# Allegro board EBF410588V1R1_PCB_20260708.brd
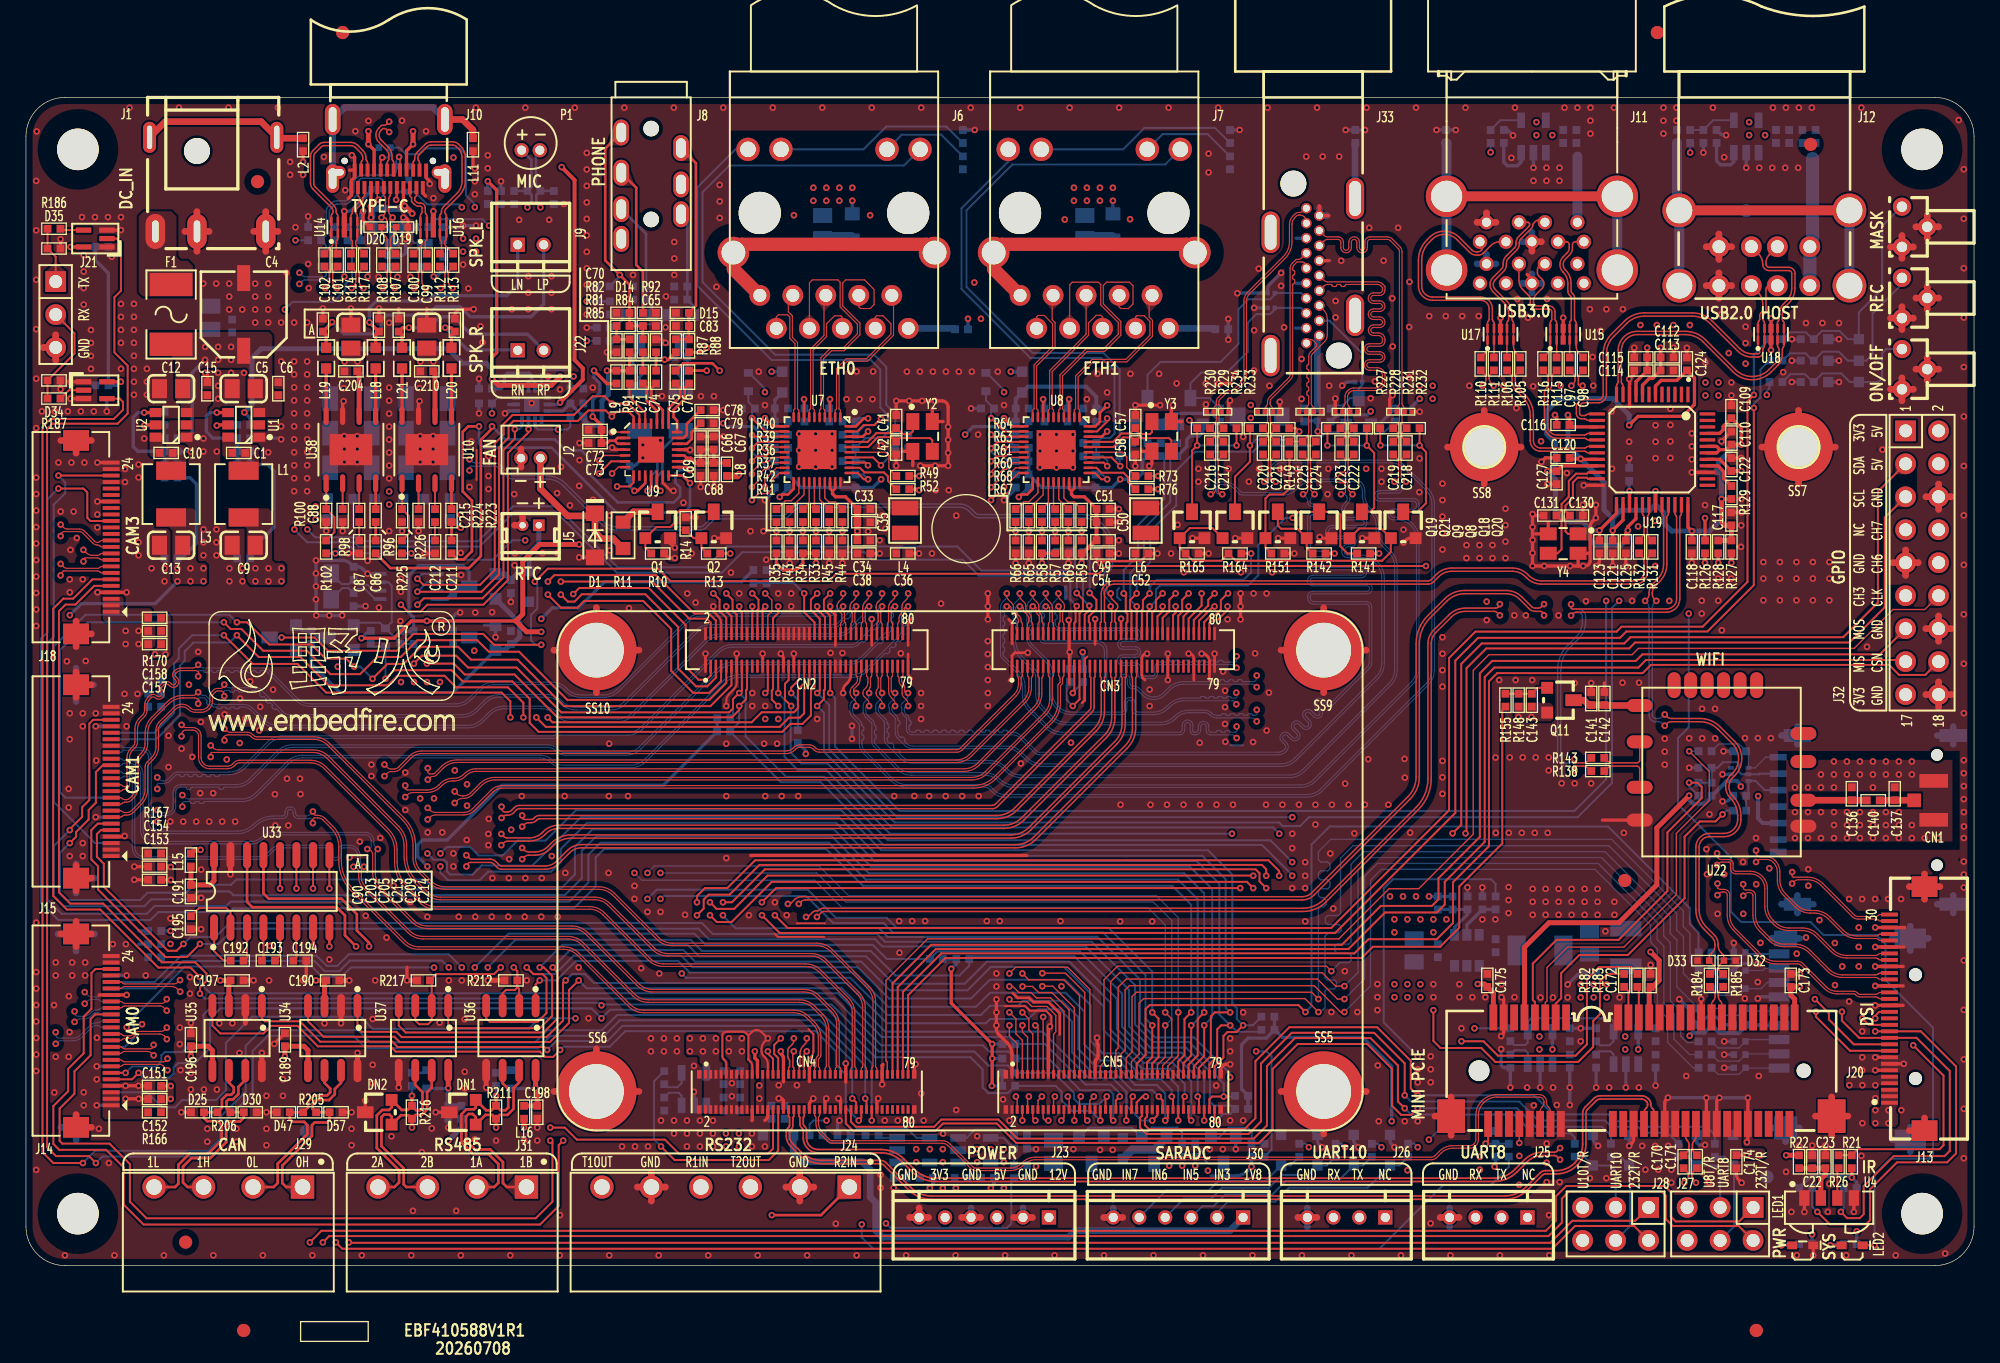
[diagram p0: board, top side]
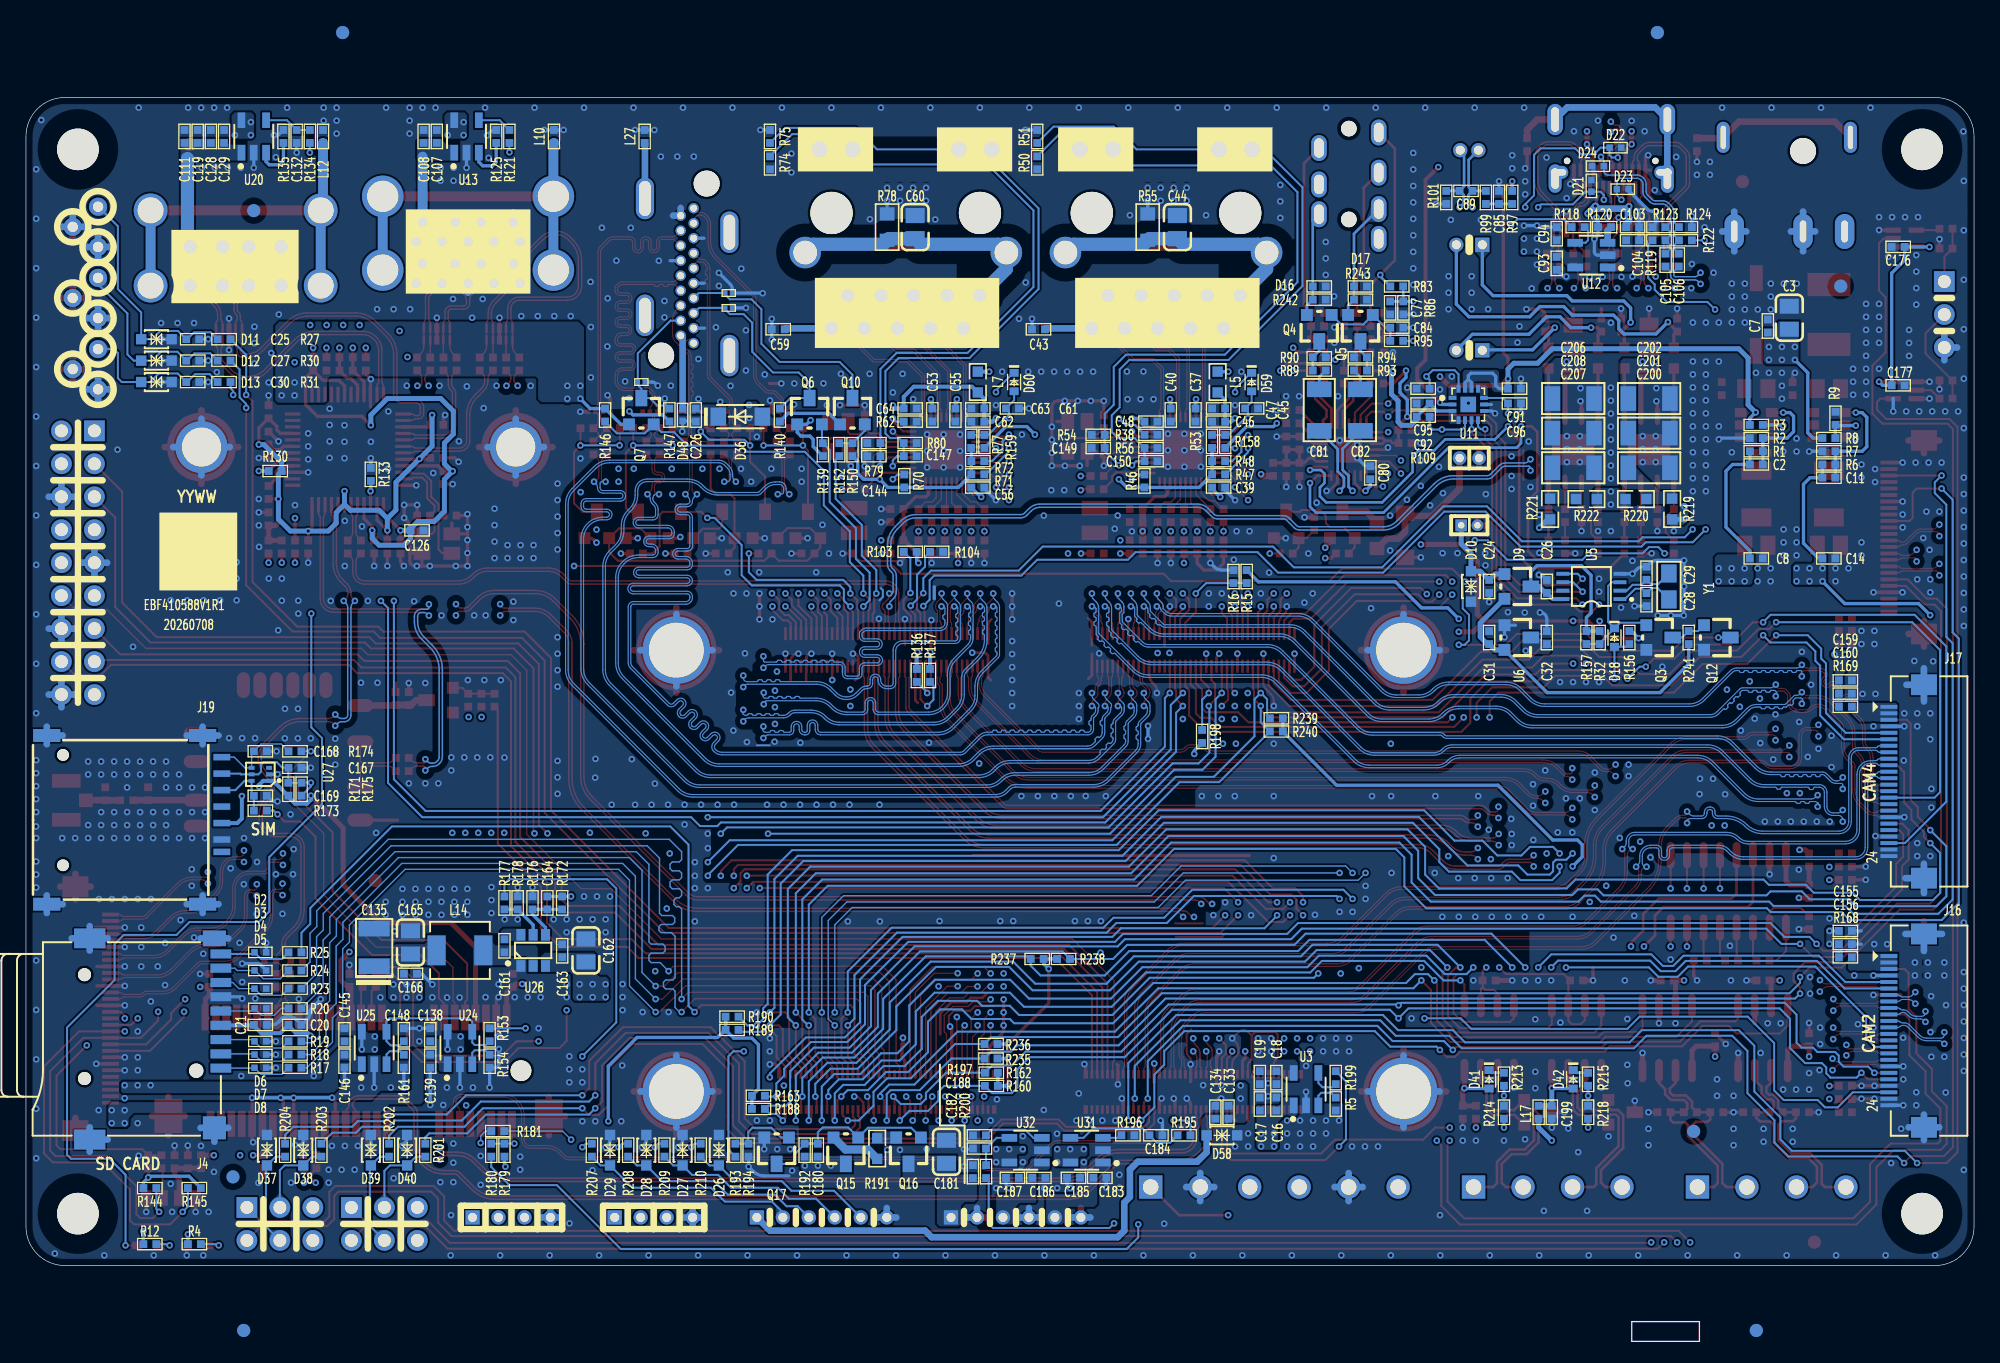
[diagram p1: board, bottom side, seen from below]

Outline 150 x 90 mm; copper layers: TOP, GND02, ART03, ART04, PWR05, BOTTOM. Coordinates in mm from the lower left corner of the outline.
Outline path: 0,87 0,3 arc(0.88,0.88) 3,0 147,0 arc(149.12,0.88) 150,3 150,87 arc(149.12,89.12) 147,90 3,90 arc(0.88,89.12) 0,87

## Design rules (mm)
constraint set DEFAULT: min track width 0.152
net group DP_TX_AUXN: nets DP_TX_AUXN SUB2
net group DP_TX_AUXP: nets DP_TX_AUXP SUB1
net group ETH0_MCLK_M0: nets ETH0_MCLK_M0 N16970797
net group ETH0_RXCLK_M0: nets ETH0_RXCLK_M0 N16970779
net group ETH0_RXCTL_M0: nets ETH0_RXCTL_M0 N16970777
net group ETH0_RXD0_M0: nets ETH0_RXD0_M0 N16970775
net group ETH0_RXD1_M0: nets ETH0_RXD1_M0 N16970773
net group ETH0_RXD2_M0: nets ETH0_RXD2_M0 N16970771
net group ETH0_RXD3_M0: nets ETH0_RXD3_M0 N16970781
net group ETH1_MCLK_M0: nets ETH1_MCLK_M0 N16976515
net group ETH1_RXCLK_M0: nets ETH1_RXCLK_M0 N16976509
net group ETH1_RXCTL_M0: nets ETH1_RXCTL_M0 N16976499
net group ETH1_RXD0_M0: nets ETH1_RXD0_M0 N16976501
net group ETH1_RXD1_M0: nets ETH1_RXD1_M0 N16976503
net group ETH1_RXD2_M0: nets ETH1_RXD2_M0 N16976505
net group ETH1_RXD3_M0: nets ETH1_RXD3_M0 N16976507
net group HDMI_TX_D0N: nets HDMI_TX_D0N HDMI_TX_D0N_PORT
net group HDMI_TX_D0P: nets HDMI_TX_D0P HDMI_TX_D0P_PORT
net group HDMI_TX_D1N: nets HDMI_TX_D1N HDMI_TX_D1N_PORT
net group HDMI_TX_D1P: nets HDMI_TX_D1P HDMI_TX_D1P_PORT
net group HDMI_TX_D2N: nets HDMI_TX_D2N HDMI_TX_D2N_PORT
net group HDMI_TX_D2P: nets HDMI_TX_D2P HDMI_TX_D2P_PORT
net group HDMI_TX_D3N: nets HDMI_TX_D3N HDMI_TX_D3N_PORT
net group HDMI_TX_D3P: nets HDMI_TX_D3P HDMI_TX_D3P_PORT
net group HDMI_TX_EARC+: nets HDMI_TX_EARC+ HDMI_TX_SBDP
net group HDMI_TX_EARC-: nets HDMI_TX_EARC- HDMI_TX_SBDN
net group PCIE0_CLKREQN_M0: nets N17044212 PCIE0_CLKREQN_M0
net group PCIE0_REFCLK: nets PCIE0_REFCLKN PCIE0_REFCLKP
net group PCIE0_RX: nets PCIE0_RXN PCIE0_RXP
net group PCIE0_TXN: nets PCIE0_TXN PE_TXN
net group PCIE0_TXP: nets PCIE0_TXP PE_TXP
net group PCIE0_WAKEN_M0: nets N17043933 PCIE0_WAKEN_M0
net group PWM0_CH0_M0_IR: nets N16966392 PWM0_CH0_M0_IR
net group RMII0_M0: nets RMII0_MDIN0 RMII0_MDIP0
net group RMII0_M1: nets RMII0_MDIN1 RMII0_MDIP1
net group RMII0_M2: nets RMII0_MDIN2 RMII0_MDIP2
net group RMII0_M3: nets RMII0_MDIN3 RMII0_MDIP3
net group RMII1_M0: nets RMII1_MDIN0 RMII1_MDIP0
net group RMII1_M1: nets RMII1_MDIN1 RMII1_MDIP1
net group RMII1_M2: nets RMII1_MDIN2 RMII1_MDIP2
net group RMII1_M3: nets RMII1_MDIN3 RMII1_MDIP3
net group SDMMC0_CLK: nets N16965209 SDMMC0_CLK
net group SDMMC0_CMD: nets N16965205 SDMMC0_CMD
net group SDMMC0_D0: nets N16965213 SDMMC0_D0
net group SDMMC0_D1: nets N16965217 SDMMC0_D1
net group SDMMC0_D2: nets N16965184 SDMMC0_D2
net group SDMMC0_D3: nets N16965201 SDMMC0_D3
net group SDMMC0_DETN: nets N16965221 SDMMC0_DETN
net group SIM_CLK0: nets N17036090 SIM_CLK0
net group TYPEC_DM: nets TYPEC_DM USB2_OTG0_DM
net group TYPEC_DP: nets TYPEC_DP USB2_OTG0_DP
net group TYPEC_SSRXN1: nets TYPEC_SSRXN1 USB3_OTG0_SSRX1N
net group TYPEC_SSRXN2: nets TYPEC_SSRXN2 USB3_OTG0_SSRX2N
net group TYPEC_SSRXP1: nets TYPEC_SSRXP1 USB3_OTG0_SSRX1P
net group TYPEC_SSRXP2: nets TYPEC_SSRXP2 USB3_OTG0_SSRX2P
net group TYPEC_SSTXN1: nets TYPEC_SSTXN1 USB3_OTG0_SSTX1N
net group TYPEC_SSTXN2: nets TYPEC_SSTXN2 USB3_OTG0_SSTX2N
net group TYPEC_SSTXP1: nets TYPEC_SSTXP1 USB3_OTG0_SSTX1P
net group TYPEC_SSTXP2: nets TYPEC_SSTXP2 USB3_OTG0_SSTX2P
net group USB2_OTG1_DM: nets N17161102 USB2_OTG1_DM
net group USB2_OTG1_DP: nets N17161099 USB2_OTG1_DP
net group USB20_DM2: nets USB20_DM2 USB_HUB_DM2
net group USB20_DP2: nets USB20_DP2 USB_HUB_DP2
net group USB30_DM: nets USB30_DM USB_HUB_DM1
net group USB30_DP: nets USB30_DP USB_HUB_DP1
net group USB30_RXN: nets USB3_OTG1_SSRXN USB30_RXN
net group USB30_RXP: nets USB3_OTG1_SSRXP USB30_RXP
net group USB30_TXN: nets USB3_OTG1_SSTXN USB30_TXN
net group USB30_TXP: nets USB3_OTG1_SSTXP USB30_TXP
net group USB_HUB_D3: nets USB_HUB_DM3 USB_HUB_DP3
net group USB_HUB_D4: nets USB_HUB_DM4 USB_HUB_DP4
net group USB_HUB_DM5: nets N17046088 USB_HUB_DM5
net group USB_HUB_DM6: nets N17367190 USB_HUB_DM6
net group USB_HUB_DP5: nets N17046085 USB_HUB_DP5
net group USB_HUB_DP6: nets N17367118 USB_HUB_DP6
net group 50OHM: nets SAI1_LRCK_M0 SAI1_MCLK_M0 SAI1_SCLK_M0 SPI1_CLK_M0
net group PWR: nets 3V3_WLAN RMII0_AVDD33 RMII1_AVDD33 RS485_1_3V3 RS485_2_3V3 SIM_VDD USB_HUB_3V3 USB_HUB_3V3_OUT USB_HUB_5V0 VCC3V3_RTC_S5 VCC_RTC

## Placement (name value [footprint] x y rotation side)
C1  0.1uF  [C0402]  16.38 62.61 0 top
C2  NC  [C0402]  16.76 61.72 0 bottom
C3  22uF  [C0805]  14.22 73.03 90 bottom
C4  100uF  [EC6P3]  16.76 73.28 180 top
C5  22uF  [C0805]  16.76 67.56 180 top
C6  0.1uF  [C0402]  19.43 67.56 90 top
C7  0.1uF  [C0402]  15.88 72.39 90 bottom
C8  0.1uF  [C0402]  16.76 54.48 180 bottom
C9  22uF  [C0805]  16.76 55.5 180 top
C10  0.1uF  [C0402]  10.79 62.61 0 top
C11  NC  [C0402]  11.18 60.71 0 bottom
C12  22uF  [C0805]  11.18 67.56 180 top
C13  22uF  [C0805]  11.18 55.5 180 top
C14  0.1uF  [C0402]  11.18 54.48 180 bottom
C15  0.1uF  [C0402]  13.97 67.56 90 top
C16  10uF  [C0402]  53.72 12.45 90 bottom
C17  0.1uF  [C0402]  54.99 12.45 90 bottom
C18  10uF  [C0402]  53.72 14.48 270 bottom
C19  0.1uF  [C0402]  54.99 14.48 270 bottom
C20  10uF  [C0402]  129.29 18.54 180 bottom
C21  0.1uF  [C0402]  131.95 18.54 180 bottom
C22  10uF  [C0402]  137.54 8 90 top
C23  0.1uF  [C0402]  138.56 8 90 top
C24  10uF  [C0402]  37.34 52.32 270 bottom
C25  NC  [C0402]  137.16 71.37 180 bottom
C26  0.1uF  [C0402]  32.89 52.32 90 bottom
C27  NC  [C0402]  137.16 69.72 180 bottom
C28  18pF  [C0402]  25.22 51.31 270 bottom
C29  18pF  [C0402]  25.22 53.34 90 bottom
C30  0.1uF  [C0402]  137.16 68.07 180 bottom
C31  1uF  [C0402]  37.34 48.39 90 bottom
C32  1uF  [C0402]  32.89 48.39 90 bottom
C33  10uF  [C0402]  64.52 58.29 0 top
C34  0.1uF  [C0402]  64.52 55.88 0 top
C35  0.1uF  [C0402]  64.52 57.28 0 top
C36  10uF  [C0402]  67.51 54.86 0 top
C37  0.1uF  [C0402]  59.94 65.53 270 bottom
C38  0.1uF  [C0402]  64.52 54.86 180 top
C39  0.1uF  [C0402]  58.17 59.94 180 bottom
C40  0.1uF  [C0402]  61.85 65.53 270 bottom
C41  18pF  [C0402]  67.01 65.02 90 top
C42  18pF  [C0402]  67.01 62.99 270 top
C43  0.1uF  [C0402]  72.03 72.14 0 bottom
C44  1nF  [C0805]  61.34 80.01 90 bottom
C45  0.1uF  [C0402]  55.63 66.04 180 bottom
C46  10uF  [C0402]  58.17 65.02 0 bottom
C47  0.1uF  [C0402]  58.17 66.04 0 bottom
C48  0.1uF  [C0402]  63.37 65.02 180 bottom
C49  10uF  [C0402]  82.93 55.88 0 top
C50  0.1uF  [C0402]  82.93 57.28 0 top
C51  0.1uF  [C0402]  82.93 58.29 0 top
C52  10uF  [C0402]  85.92 54.86 0 top
C53  0.1uF  [C0402]  80.21 65.53 270 bottom
C54  0.1uF  [C0402]  82.93 54.86 180 top
C55  0.1uF  [C0402]  78.43 65.53 270 bottom
C56  0.1uF  [C0402]  76.71 59.94 180 bottom
C57  18pF  [C0402]  85.42 65.02 90 top
C58  18pF  [C0402]  85.42 62.99 270 top
C59  0.1uF  [C0402]  92.08 72.14 0 bottom
C60  1nF  [C0805]  81.53 80.01 90 bottom
C61  0.1uF  [C0402]  74.04 66.04 180 bottom
C62  10uF  [C0402]  76.71 65.02 0 bottom
C63  0.1uF  [C0402]  76.71 66.04 0 bottom
C64  0.1uF  [C0402]  81.92 66.04 180 bottom
C65  270pF  [C0402]  48.01 72.39 0 top
C66  0.1uF  [C0402]  51.94 63.37 90 top
C67  0.1uF  [C0402]  52.96 63.37 90 top
C68  10uF  [C0402]  52.96 61.34 270 top
C69  10uF  [C0402]  51.94 61.34 270 top
C70  10uF  [C0402]  45.47 70.87 270 top
C71  1uF  [C0402]  47.5 68.45 90 top
C72  0.1uF  [C0402]  43.81 64.39 180 top
C73  10uF  [C0402]  43.81 63.37 180 top
C74  1uF  [C0402]  48.51 68.45 90 top
C75  1uF  [C0402]  50.04 68.45 90 top
C76  1uF  [C0402]  51.05 68.45 90 top
C77  NC  [C0402]  44.96 73.79 270 bottom
C78  10uF  [C0402]  52.45 65.91 0 top
C79  10uF  [C0402]  52.45 64.9 0 top
C80  10uF  [C0402]  46.48 61.09 90 bottom
C81  47uF  [C1206]  50.42 65.91 270 bottom
C82  47uF  [C1206]  47.24 65.91 270 bottom
C83  0.1uF  [C0402]  50.55 72.39 180 top
C84  0.1uF  [C0402]  44.45 72.26 180 bottom
C85  10uF  [C0402]  36.58 82.3 90 bottom
C86  0.1uF  [C0402]  26.92 55.37 90 top
C87  0.1uF  [C0402]  25.65 55.37 90 top
C88  1uF  [C0402]  24.38 57.78 270 top
C89  100pF  [C0402]  39.12 82.8 0 bottom
C90  1nF  [C0402]  22.86 72.46 90 top
C91  0.1uF  [C0402]  35.38 67.56 180 bottom
C92  10uF  [C0402]  42.42 66.42 0 bottom
C93  10uF  [C0402]  32.13 77.22 270 bottom
C94  0.1uF  [C0402]  32.13 79.5 90 bottom
C95  220pF  [C0402]  42.42 67.56 0 bottom
C96  220pF  [C0402]  35.38 66.42 180 bottom
C97  0.1uF  [C0402]  118.87 69.47 270 top
C98  0.1uF  [C0402]  119.89 69.47 270 top
C99  0.1uF  [C0402]  30.86 77.47 270 top
C100  0.1uF  [C0402]  29.84 77.47 270 top
C101  0.1uF  [C0402]  24 77.47 270 top
C102  0.1uF  [C0402]  22.99 77.47 270 top
C103  10uF  [C0402]  26.29 80.01 180 bottom
C104  0.1uF  [C0402]  26.29 78.99 180 bottom
C105  0.1uF  [C0402]  23.75 77.47 270 bottom
C106  0.1uF  [C0402]  22.73 77.47 270 bottom
C107  10uF  [C0402]  118.36 87 90 bottom
C108  0.1uF  [C0402]  119.38 87 90 bottom
C109  0.1uF  [C0402]  131.32 65.79 90 top
C110  0.1uF  [C0402]  131.32 63.75 90 top
C111  10uF  [C0402]  137.79 87 90 bottom
C112  NC  [C0402]  126.36 69.98 0 top
C113  NC  [C0402]  126.36 68.96 0 top
C114  NC  [C0402]  124.33 68.96 180 top
C115  NC  [C0402]  124.33 69.98 180 top
C116  0.1uF  [C0402]  118.36 64.77 180 top
C117  0.1uF  [C0402]  131.32 57.53 90 top
C118  0.1uF  [C0402]  128.27 55.37 270 top
C119  10uF  [C0402]  136.78 87 90 bottom
C120  0.1uF  [C0402]  118.36 62.23 180 top
C121  0.1uF  [C0402]  122.17 55.37 270 top
C122  0.1uF  [C0402]  131.32 61.72 90 top
C123  10uF  [C0402]  121.16 55.37 270 top
C124  0.1uF  [C0402]  127.89 69.47 90 top
C125  0.1uF  [C0402]  123.19 55.37 270 top
C126  0.1uF  [C0402]  119.89 56.64 180 bottom
C127  0.1uF  [C0402]  117.86 60.71 270 top
C128  10uF  [C0402]  135.76 87 90 bottom
C129  0.1uF  [C0402]  134.75 87 90 bottom
C130  NC  [C0402]  119.38 57.78 0 top
C131  NC  [C0402]  117.35 57.78 180 top
C132  0.1uF  [C0402]  129.16 87 270 bottom
C133  10uF  [C0402]  57.4 11.81 90 bottom
C134  0.1uF  [C0402]  58.42 11.81 90 bottom
C135  220uF  [CASE-B_3528]  123.19 24.51 90 bottom
C136  NC  [C0402]  140.59 36.35 90 top
C137  NC  [C0402]  143.89 36.35 90 top
C138  10uF  [C0402]  118.87 17.78 90 bottom
C139  0.1uF  [C0402]  118.87 15.75 270 bottom
C140  10pF  [C0402]  142.24 35.84 0 top
C141  10uF  [C0402]  120.52 43.69 90 top
C142  0.1uF  [C0402]  121.54 43.69 90 top
C143  0.1uF  [C0402]  115.95 43.56 90 top
C144  100pF  [C0402]  84.71 62.36 0 bottom
C145  10uF  [C0402]  125.48 17.78 90 bottom
C146  0.1uF  [C0402]  125.48 15.75 270 bottom
C147  100pF  [C0402]  81.92 62.36 180 bottom
C148  0.1uF  [C0402]  120.9 17.78 90 bottom
C149  100pF  [C0402]  67.44 62.99 0 bottom
C150  100pF  [C0402]  63.37 61.98 180 bottom
C151  10uF  [C0402]  9.91 13.84 180 top
C152  0.1uF  [C0402]  9.91 12.83 180 top
C153  10uF  [C0402]  9.91 29.72 180 top
C154  0.1uF  [C0402]  9.91 30.73 180 top
C155  10uF  [C0402]  9.91 25.78 180 bottom
C156  0.1uF  [C0402]  9.91 24.77 180 bottom
C157  10uF  [C0402]  9.91 47.88 180 top
C158  0.1uF  [C0402]  9.91 48.9 180 top
C159  10uF  [C0402]  9.91 45.09 180 bottom
C160  0.1uF  [C0402]  9.91 44.07 180 bottom
C161  0.1uF  [C0402]  113.16 24.64 270 bottom
C162  22uF  [C0805]  106.88 24.28 90 bottom
C163  0.1uF  [C0402]  108.71 24.26 90 bottom
C164  NC  [C0402]  109.86 27.94 90 bottom
C165  22uF  [C0805]  120.4 24.89 90 bottom
C166  0.1uF  [C0402]  120.4 22.48 180 bottom
C167  33pF  [C0402]  129.29 38.35 180 bottom
C168  33pF  [C0402]  131.95 39.62 180 bottom
C169  33pF  [C0402]  131.95 36.2 180 bottom
C170  0.1uF  [C0402]  127.64 8 90 top
C171  0.1uF  [C0402]  128.65 8 90 top
C172  0.1uF  [C0402]  125.09 21.97 90 top
C173  0.1uF  [C0402]  135.89 21.97 90 top
C174  0.1uF  [C0402]  131.7 8 270 top
C175  0.1uF  [C0402]  112.52 21.97 90 top
C176  0.1uF  [C0402]  5.84 78.49 0 bottom
C177  0.1uF  [C0402]  5.84 67.82 180 bottom
C180  0.1uF  [C0402]  89.03 8.89 90 bottom
C181  22uF  [C0805]  79.12 8.76 90 bottom
C182  0.1uF  [C0402]  77.09 7.24 90 bottom
C183  10uF  [C0402]  67.31 6.76 180 bottom
C184  0.1uF  [C0402]  62.99 10.03 180 bottom
C185  0.1uF  [C0402]  69.34 6.76 0 bottom
C186  10uF  [C0402]  72.01 6.76 180 bottom
C187  0.1uF  [C0402]  74.04 6.76 0 bottom
C188  0.1uF  [C0402]  76.58 9.02 0 bottom
C189  0.1uF  [C0402]  19.94 17.4 90 top
C190  0.1uF  [C0402]  23.62 21.97 0 top
C191  0.1uF  [C0402]  12.7 28.83 270 top
C192  0.1uF  [C0402]  16.26 23.5 180 top
C193  0.1uF  [C0402]  18.67 23.5 180 top
C194  0.1uF  [C0402]  21.08 23.5 0 top
C195  0.1uF  [C0402]  12.7 26.42 270 top
C196  0.1uF  [C0402]  12.7 17.4 90 top
C197  0.1uF  [C0402]  16.26 21.97 0 top
C198  0.1uF  [C0402]  39.37 11.81 270 top
C199  0.1uF  [C0402]  32.51 11.81 270 bottom
C200  47uF  [C1206]  25.02 61.47 180 bottom
C201  47uF  [C1206]  25.02 64.14 180 bottom
C202  47uF  [C1206]  25.02 66.8 180 bottom
C203  22uF  [C0805]  25.02 71.57 90 top
C204  0.1uF  [C0402]  25.02 68.9 180 top
C205  1nF  [C0402]  27.18 72.46 90 top
C206  47uF  [C1206]  30.86 66.8 180 bottom
C207  47uF  [C1206]  30.86 61.47 180 bottom
C208  47uF  [C1206]  30.86 64.14 180 bottom
C209  22uF  [C0805]  30.86 71.57 90 top
C210  0.1uF  [C0402]  30.86 68.9 180 top
C211  0.1uF  [C0402]  32.77 55.37 90 top
C212  0.1uF  [C0402]  31.5 55.37 90 top
C213  1nF  [C0402]  28.7 72.46 90 top
C214  1nF  [C0402]  33.02 72.46 90 top
C215  1uF  [C0402]  30.23 57.78 270 top
C216  0.22uF  [C0402]  91.19 62.99 90 top
C217  0.22uF  [C0402]  92.2 62.99 90 top
C218  0.22uF  [C0402]  106.3 62.99 90 top
C219  0.22uF  [C0402]  105.28 62.99 90 top
C220  0.22uF  [C0402]  95.25 62.99 90 top
C221  0.22uF  [C0402]  96.27 62.99 90 top
C222  0.22uF  [C0402]  102.23 62.99 90 top
C223  0.22uF  [C0402]  101.22 62.99 90 top
C224  1uF  [C0402]  99.31 62.99 90 top
C225  1uF  [C0402]  98.3 62.99 90 top
C226  1uF  [C0402]  98.42 65.53 270 bottom
CN1  WiFi-Ant  [UFL-3]  146.89 35.84 270 top
CN2  DF40C-80DS-0.4V(51)  [DF40C-80DS-0P4V]  60.12 47.45 0 top
CN3  DF40C-80DS-0.4V(51)  [DF40C-80DS-0P4V]  83.72 47.45 0 top
CN4  DF40C-80DP-0.4V(51)  [DF40C-80DP-0P4V]  60.12 13.38 0 top
CN5  DF40C-80DP-0.4V(51)  [DF40C-80DP-0P4V]  83.72 13.38 0 top
D1  1N4148W  [SOD-123]  43.81 56.26 90 top
D2  KLXES15AAA1  [ES0402]  131.95 24.13 0 bottom
D3  KLXES15AAA1  [ES0402]  131.95 22.73 0 bottom
D4  KLXES15AAA1  [ES0402]  131.95 21.34 0 bottom
D5  KLXES15AAA1  [ES0402]  131.95 19.81 0 bottom
D6  KLXES15AAA1  [ES0402]  131.95 17.27 0 bottom
D7  KLXES15AAA1  [ES0402]  131.95 16.26 0 bottom
D8  KLXES15AAA1  [ES0402]  131.95 15.24 0 bottom
D9  BAT54C  [SOT23]  35.17 52.32 270 bottom
D10  PESD3V3L1BA  [SOD323_T]  38.73 52.32 90 bottom
D11  PESD3V3L1BA  [SOD323_T]  139.95 71.37 0 bottom
D12  PESD3V3L1BA  [SOD323_T]  139.95 69.72 0 bottom
D13  PESD3V3L1BA  [SOD323_T]  139.95 68.07 0 bottom
D14  D2315-5R0B  [ESD0402]  45.97 73.41 0 top
D15  D2315-5R0B  [ESD0402]  50.55 73.41 0 top
D16  D2315-5R0B  [ESD0402]  50.42 75.44 0 bottom
D17  D2315-5R0B  [ESD0402]  47.24 75.44 0 bottom
D18  B5819WT  [SOD523]  27.69 48.39 270 bottom
D19  KLXES15AAA1  [ES0402]  28.96 80.01 180 top
D20  KLXES15AAA1  [ES0402]  26.92 80.01 0 top
D21  KLXES15AAA1  [ES0402]  29.46 83.19 270 bottom
D22  KLXES15AAA1  [ES0402]  27.61 86.13 0 bottom
D23  KLXES15AAA1  [ES0402]  27.05 82.93 0 bottom
D24  KLXES15AAA1  [ES0402]  28.96 84.71 180 bottom
D25  D2315-5R0B  [ESD0402]  13.21 11.81 180 top
D26  PESD3V3L1BA  [SOD323_T]  96.65 8.89 270 bottom
D27  PESD3V3L1BA  [SOD323_T]  99.44 8.89 270 bottom
D28  PESD3V3L1BA  [SOD323_T]  102.23 8.89 270 bottom
D29  PESD3V3L1BA  [SOD323_T]  105.03 8.89 270 bottom
D30  D2315-5R0B  [ESD0402]  17.27 11.81 0 top
D31  TPESD0201G05V  [R0201]  98.3 65.79 0 top
D32  KLXES15AAA1  [ES0402]  131.19 23.5 0 top
D33  KLXES15AAA1  [ES0402]  129.16 23.5 180 top
D34  D2315-3R3  [ESD0402]  2.16 68.2 180 top
D35  D2315-3R3  [ESD0402]  2.16 78.36 180 top
D36  1N5819W  [SOD-123]  95 65.41 0 bottom
D37  PESD3V3L1BA  [SOD323_T]  131.44 8.89 270 bottom
D38  PESD3V3L1BA  [SOD323_T]  128.65 8.89 270 bottom
D39  PESD3V3L1BA  [SOD323_T]  123.44 8.89 270 bottom
D40  PESD3V3L1BA  [SOD323_T]  120.65 8.89 270 bottom
D41  RB521S-30  [SOD523]  37.34 14.35 270 bottom
D42  RB521S-30  [SOD523]  30.86 14.35 270 bottom
D43  TPESD0201G05V  [R0201]  95.89 74.93 0 bottom
D44  TPESD0201G05V  [R0201]  99.44 65.79 180 top
D45  TPESD0201G05V  [R0201]  95.89 73.79 0 bottom
D46  TPESD0201G05V  [R0201]  102.62 68.07 0 bottom
D47  D2315-5R0B  [ESD0402]  19.81 11.81 180 top
D48  KLXES15AAA1  [ES0402]  99.44 65.53 270 bottom
D49  TPESD0201G05V  [R0201]  95.12 65.79 0 top
D50  TPESD0201G05V  [R0201]  96.27 65.79 180 top
D51  TPESD0201G05V  [R0201]  102.23 65.79 180 top
D52  TPESD0201G05V  [R0201]  101.09 65.79 0 top
D53  TPESD0201G05V  [R0201]  91.19 65.79 0 top
D54  TPESD0201G05V  [R0201]  92.33 65.79 180 top
D55  TPESD0201G05V  [R0201]  106.43 65.79 180 top
D56  TPESD0201G05V  [R0201]  105.28 65.79 0 top
D57  D2315-5R0B  [ESD0402]  23.88 11.81 0 top
D58  PESD3V3L1BA  [SOD323_T]  57.91 10.03 0 bottom
D59  RB521S-30  [SOD523]  55.63 68.07 270 bottom
D60  RB521S-30  [SOD523]  73.91 68.07 270 bottom
DN1  SM712  [SOT23]  33.64 11.81 90 top
DN2  SM712  [SOT23]  27.17 11.81 90 top
F1  SMD1812P200TF16  [F1812]  11.18 73.28 270 top
J1  DC-044A-20A  [DC_IN_TH_3P_10R1X11R6]  14.41 84.18 270 top
J2  A1501WV-2P  [ZH1P5MM_TH_2P]  38.86 62.21 180 top
J4  TF_Card  [TFCARD]  145.49 18.41 270 bottom
J5  1.25T-2A  [GH1P25_TH_2P]  38.86 57.04 180 top
J6  -  [HY911130A]  62.22 81.1 0 top
J7  -  [HY911130A]  82.26 81.1 0 top
J8  PJ-393-7P  [AV7_6X14R50_TM]  48.14 84.1 0 top
J9  PH-2A  [PH-1X2-2P0_L]  38.86 78.65 0 top
J10  TYPE-C  [USB-C-SMD_TYC-324G]  27.93 85.68 180 top
J11  USB3D0_USB2D0-A-D  [USB3D0-AF-18P]  115.96 78.88 180 top
J12  -  [USB-A-D]  133.86 82 0 top
J13  FPC_0R5_30P_D  [FPC-30P-0P5]  144.84 19.8 90 top
J14  FPC_0P5_24P_D  [FPC_24P_0P5]  5.21 18.1 90 top
J15  FPC_0P5_24P_D  [FPC_24P_0P5]  5.21 37.3 90 top
J16  FPC_0P5_24P_D  [FPC_24P_0P5]  5.21 18.1 270 bottom
J17  FPC_0P5_24P_D  [FPC_24P_0P5]  5.21 37.3 270 bottom
J18  FPC_0P5_24P_D  [FPC_24P_0P5]  5.21 56.12 90 top
J19  SIM-7-1  [NANO_SIM]  141.66 34.34 270 bottom
J20  MINI-PCIE  [PCIE_52P]  124.39 15.01 0 top
J21  -  [HDR1X3-2R54-TM-VM]  2.29 73.27 270 top
J22  PH-2A  [PH-1X2-2P0_L]  38.86 70.52 0 top
J23  PH-6A  [PH-1X6-2P0]  73.77 3.71 180 top
J24  CON6  [DB2ERC-3P81-6P]  53.87 6.05 180 top
J25  PH-4A  [PH-1X4-2P0]  112.62 3.71 180 top
J26  PH-4A  [PH-1X4-2P0]  101.67 3.71 180 top
J27  -  [HDR2X3-2R54-TM-VM]  130.45 3.21 180 top
J28  -  [HDR2X3-2R54-TM-VM]  122.4 3.21 180 top
J29  WJ15EDGRC-3.81-4P  [DB2ERC-3P81-4P]  15.58 6.05 180 top
J30  PH-6A  [PH-1X6-2P0]  88.72 3.71 180 top
J31  WJ15EDGRC-3.81-4P  [DB2ERC-3P81-4P]  32.82 6.05 180 top
J32  -  [HDR2X9-2R54-TM-VM]  146 54.15 270 top
J33  HDMI-001C  [HDMI-SMD]  99.09 76.16 90 top
L1  3.3uH  [L4520]  16.76 59.44 270 top
L2  120R 100MHz  [L0402]  21.34 86.36 270 top
L3  3.3uH  [L4520]  11.17 59.44 270 top
L4  2.2uH  [L2520]  67.69 57.4 270 top
L5  330R 100MHz  [L0603]  58.24 68.07 270 bottom
L6  2.2uH  [L2520]  86.23 57.4 270 top
L7  330R 100MHz  [L0603]  76.71 68.07 270 bottom
L8  120R 100MHz  [L0402]  53.98 61.34 90 top
L9  120R 100MHz  [L0402]  45.47 68.45 270 top
L10  120R 100MHz  [L0402]  109.35 87 90 bottom
L11  120R 100MHz  [L0402]  34.42 86.36 270 top
L12  120R 100MHz  [L0402]  127.13 87 90 bottom
L14  3.3uH  [L4520]  116.58 24.28 0 bottom
L15  120R 100MHz  [L0402]  12.7 31.24 90 top
L16  120R 100MHz  [L0402]  38.35 11.81 90 top
L17  120R 100MHz  [L0402]  33.53 11.81 90 bottom
L18  1K 100MHz  [L0603]  26.92 69.92 90 top
L19  1K 100MHz  [L0603]  23.11 69.92 90 top
L20  1K 100MHz  [L0603]  32.77 69.92 90 top
L21  1K 100MHz  [L0603]  28.96 69.92 90 top
L27  120R 100MHz  [L0402]  102.36 87 270 bottom
LED1  HS-0602-UR  [LED_HS_0602_UR]  136.81 1.56 180 top
LED2  HS-0602-UG  [LED_HS_0602_UR]  140.62 1.56 180 top
NOREF  -  []  143 -1 0 top
NOREF#2  -  []  75 -1 0 top
NOREF#3  -  [unnamed#2]  16.76 -5 0 top
NOREF#4  -  [unnamed#2]  133.24 -5 0 top
NOREF#5  -  []  7 91 180 top
NOREF#6  -  []  140.34 -25.43 0 top
NOREF#7  -  []  7 -1 0 top
NOREF#8  -  []  75 91 180 top
NOREF#9  -  [unnamed#2]  125.62 95 180 top
NOREF#10  -  [unnamed#2]  24.38 95 180 top
NOREF#11  -  []  0 3 0 top
NOREF#12  -  []  3 0 90 top
NOREF#13  -  [unnamed#2]  137.41 86.39 180 top
NOREF#14  -  []  143 91 180 top
NOREF#15  -  [unnamed#2]  12.29 1.8 180 top
NOREF#16  -  [unnamed#2]  123.11 29.67 180 top
NOREF#17  -  [unnamed#2]  17.83 83.52 180 top
NOREF#18  -  [unnamed#2]  24.38 95 0 bottom
NOREF#19  -  [unnamed#2]  125.62 95 0 bottom
NOREF#20  -  [unnamed#2]  21.59 10.34 180 bottom
NOREF#21  -  [unnamed#2]  132.46 81.28 180 bottom
NOREF#22  -  [unnamed#2]  134.06 6.83 180 bottom
NOREF#23  -  [unnamed#2]  10.26 75.46 180 bottom
NOREF#24  -  [unnamed#2]  16.76 -5 180 bottom
NOREF#25  -  [unnamed#2]  133.24 -5 180 bottom
P1  MIC_POM  [MIC2-4R00-TM]  38.86 85.94 0 top
Q1  SSM3J328R-LF  [SOT23]  48.64 57.04 0 top
Q2  SS8050  [SOT23]  52.96 57.04 0 top
Q3  2SK3018  [SOT23]  24.24 48.39 270 bottom
Q4  WNM2016-3/TR  [SOT23]  50.42 72.25 0 bottom
Q5  WNM2016-3/TR  [SOT23]  47.24 72.25 0 bottom
Q6  2SK3018  [SOT23]  89.66 65.8 180 bottom
Q7  2SK3018  [SOT23]  102.62 65.8 180 bottom
Q8  2SK3018  [SOT23]  99.57 57.04 0 top
Q9  2SK3018  [SOT23]  96.39 57.04 0 top
Q10  2SK3018  [SOT23]  86.36 65.8 180 bottom
Q11  AO3407  [SOT23]  118.12 43.56 270 top
Q12  2SK3018  [SOT23]  19.8 48.39 270 bottom
Q15  AO3407  [SOT23]  86.87 8.88 0 bottom
Q16  AO3407  [SOT23]  82.04 8.88 0 bottom
Q17  SS8050  [SOT23]  92.2 8.88 0 bottom
Q18  2SK3018  [SOT23]  102.87 57.04 0 top
Q19  2SK3018  [SOT23]  89.79 57.04 0 top
Q20  2SK3018  [SOT23]  106.05 57.04 0 top
Q21  2SK3018  [SOT23]  93.09 57.04 0 top
R1  115K  [R0402]  16.76 62.74 0 bottom
R2  20K  [R0402]  16.76 63.75 0 bottom
R3  10K  [R0402]  16.76 64.77 180 bottom
R4  5.1K  [R0402]  137.03 1.65 180 bottom
R5  3.4K  [R0402]  49.15 12.45 270 bottom
R6  115K  [R0402]  11.18 61.72 0 bottom
R7  20K  [R0402]  11.18 62.74 0 bottom
R8  180K  [R0402]  11.18 63.75 0 bottom
R9  27K  [R0402]  10.67 65.28 90 bottom
R10  10K  [R0402]  48.64 54.86 180 top
R11  0R  [R0805]  45.97 56.26 270 top
R12  4.7K  [R0402]  140.46 1.65 180 bottom
R13  1K  [R0402]  52.96 54.86 180 top
R14  10K  [R0402]  50.8 57.15 90 top
R15  25.5K  [R0402]  56.01 53.09 270 bottom
R16  10K  [R0402]  57.02 53.09 90 bottom
R17  22R  [R0402]  129.29 15.24 0 bottom
R18  22R  [R0402]  129.29 16.26 0 bottom
R19  22R  [R0402]  129.29 17.27 0 bottom
R20  22R  [R0402]  129.29 19.81 0 bottom
R21  10K  [R0402]  140.59 8 90 top
R22  22R  [R0402]  136.53 8 270 top
R23  22R  [R0402]  129.29 21.34 0 bottom
R24  22R  [R0402]  129.29 22.73 0 bottom
R25  22R  [R0402]  129.29 24.13 0 bottom
R26  22R  [R0402]  139.57 8 270 top
R27  100R  [R0402]  134.75 71.37 180 bottom
R30  100R  [R0402]  134.75 69.72 180 bottom
R31  100R  [R0402]  134.75 68.07 180 bottom
R32  NC  [R0402]  28.83 48.39 270 bottom
R33  4.7K  [R0402]  60.83 55.37 90 top
R34  4.7K  [R0402]  59.82 55.37 90 top
R35  4.7K  [R0402]  57.78 55.37 90 top
R36  22R  [R0402]  59.82 57.78 90 top
R37  22R  [R0402]  60.83 57.78 90 top
R38  2.49K  [R0402]  63.37 64.01 180 bottom
R39  22R  [R0402]  58.8 57.78 90 top
R40  22R  [R0402]  57.78 57.78 90 top
R41  22R  [R0402]  62.87 57.78 90 top
R42  22R  [R0402]  61.85 57.78 90 top
R43  4.7K  [R0402]  58.8 55.37 270 top
R44  4.7K  [R0402]  62.87 55.37 270 top
R45  4.7K  [R0402]  61.85 55.37 270 top
R46  4.7K  [R0402]  63.88 60.45 90 bottom
R47  4.7K  [R0402]  58.17 60.96 180 bottom
R48  4.7K  [R0402]  58.17 61.98 180 bottom
R49  22R  [R0402]  67.51 60.83 180 top
R50  510R  [R0402]  72.14 84.96 270 bottom
R51  510R  [R0402]  72.14 87 90 bottom
R52  4.7K  [R0402]  67.51 59.82 0 top
R53  10K  [R0402]  58.67 63.5 90 bottom
R54  4.7K  [R0402]  67.44 64.01 0 bottom
R55  1M  [R0805]  63.63 80.01 90 bottom
R56  4.7K  [R0402]  63.37 62.99 180 bottom
R57  4.7K  [R0402]  79.25 55.37 90 top
R58  4.7K  [R0402]  78.23 55.37 90 top
R59  4.7K  [R0402]  81.28 55.37 90 top
R60  22R  [R0402]  79.25 57.78 90 top
R61  22R  [R0402]  78.23 57.78 90 top
R62  2.49K  [R0402]  81.92 65.02 180 bottom
R63  22R  [R0402]  77.22 57.78 90 top
R64  22R  [R0402]  76.2 57.78 90 top
R65  4.7K  [R0402]  77.22 55.37 270 top
R66  4.7K  [R0402]  76.2 55.37 270 top
R67  22R  [R0402]  81.28 57.78 90 top
R68  22R  [R0402]  80.26 57.78 90 top
R69  4.7K  [R0402]  80.26 55.37 270 top
R70  4.7K  [R0402]  82.37 60.45 90 bottom
R71  4.7K  [R0402]  76.71 60.96 180 bottom
R72  4.7K  [R0402]  76.71 61.98 180 bottom
R73  22R  [R0402]  85.92 60.83 180 top
R74  510R  [R0402]  92.71 84.96 270 bottom
R75  510R  [R0402]  92.71 87 90 bottom
R76  4.7K  [R0402]  85.92 59.82 0 top
R77  10K  [R0402]  77.22 63.5 90 bottom
R78  1M  [R0805]  83.69 80.01 90 bottom
R79  4.7K  [R0402]  84.71 63.37 0 bottom
R80  4.7K  [R0402]  81.92 63.37 180 bottom
R81  0R  [R0402]  47.5 70.87 270 top
R82  100R  [R0402]  46.48 70.87 270 top
R83  100K  [R0402]  44.45 75.44 180 bottom
R84  2.2K  [R0402]  45.97 72.39 0 top
R85  0R  [R0402]  48.51 70.87 270 top
R86  100K  [R0402]  43.94 73.79 270 bottom
R87  100K  [R0402]  50.04 70.87 90 top
R88  0R  [R0402]  51.05 70.87 270 top
R89  0R  [R0402]  50.42 68.96 180 bottom
R90  470R  [R0402]  50.42 69.98 180 bottom
R91  10K  [R0402]  46.48 68.45 270 top
R92  0R  [R0402]  48.01 73.41 0 top
R93  0R  [R0402]  47.24 68.96 0 bottom
R94  470R  [R0402]  47.24 69.98 0 bottom
R95  300K  [R0402]  44.45 71.25 180 bottom
R96  20K  [R0402]  26.92 57.78 90 top
R97  100R  [R0402]  35.56 82.3 90 bottom
R98  20K  [R0402]  25.65 57.78 90 top
R99  1K  [R0402]  37.59 82.3 90 bottom
R100  10K  [R0402]  23.11 57.78 270 top
R101  1K  [R0402]  40.64 82.3 270 bottom
R102  1K  [R0402]  23.11 55.37 90 top
R103  4.7K  [R0402]  81.92 54.99 0 bottom
R104  NC  [R0402]  79.88 54.99 0 bottom
R105  0R  [R0402]  115.06 69.47 270 top
R106  0R  [R0402]  114.05 69.47 270 top
R107  0R  [R0402]  28.45 77.47 270 top
R108  0R  [R0402]  27.43 77.47 270 top
R109  10K  [R0402]  42.42 65.41 180 bottom
R110  0R  [R0402]  112.01 69.47 270 top
R111  0R  [R0402]  113.03 69.47 270 top
R112  0R  [R0402]  31.88 77.47 270 top
R113  0R  [R0402]  32.89 77.47 270 top
R114  0R  [R0402]  25.02 77.47 270 top
R115  0R  [R0402]  117.86 69.47 270 top
R116  0R  [R0402]  116.84 69.47 270 top
R117  0R  [R0402]  26.04 77.47 270 top
R118  10K  [R0402]  30.48 80.01 180 bottom
R119  100K  [R0402]  24.26 78.99 0 bottom
R120  3.4K  [R0402]  28.45 80.01 0 bottom
R121  10K  [R0402]  112.78 87 90 bottom
R122  100K  [R0402]  22.23 78.99 180 bottom
R123  NC  [R0402]  24.26 80.01 0 bottom
R124  NC  [R0402]  22.23 80.01 180 bottom
R125  3.4K  [R0402]  113.79 87 90 bottom
R126  NC  [R0402]  129.29 55.37 270 top
R127  0R  [R0402]  131.32 55.37 90 top
R128  NC  [R0402]  130.3 55.37 90 top
R129  100K  [R0402]  131.32 59.56 270 top
R130  10K  [R0402]  130.81 61.21 180 bottom
R131  0R  [R0402]  125.22 55.37 90 top
R132  0R  [R0402]  124.21 55.37 90 top
R133  2.7K  [R0402]  123.44 60.96 90 bottom
R134  10K  [R0402]  128.14 87 90 bottom
R135  3.4K  [R0402]  130.18 87 90 bottom
R136  4.7K  [R0402]  81.41 45.47 270 bottom
R137  NC  [R0402]  80.39 45.47 270 bottom
R138  0R  [R0402]  121.03 38.1 0 top
R139  10K  [R0402]  88.65 62.87 90 bottom
R140  1.8K  [R0402]  91.95 65.53 90 bottom
R141  47K  [R0402]  103 54.86 180 top
R142  47K  [R0402]  99.57 54.86 180 top
R143  0R  [R0402]  121.03 39.12 0 top
R144  NC  [R0402]  140.46 5.97 180 bottom
R145  NC  [R0402]  137.03 5.97 0 bottom
R146  10K  [R0402]  105.41 65.53 270 bottom
R147  1.8K  [R0402]  100.46 65.53 90 bottom
R148  10K  [R0402]  114.94 43.56 90 top
R149  1.2K  [R0402]  97.28 62.99 90 top
R150  27K  [R0402]  86.36 62.87 90 bottom
R151  47K  [R0402]  96.39 54.86 0 top
R152  100R  [R0402]  87.38 62.87 90 bottom
R153  1K  [R0402]  114.3 17.78 270 bottom
R154  3.4K  [R0402]  114.3 15.75 270 bottom
R155  1K  [R0402]  113.92 43.56 90 top
R156  10K  [R0402]  26.54 48.39 270 bottom
R157  10K  [R0402]  29.84 48.39 270 bottom
R158  NC  [R0402]  57.66 63.5 90 bottom
R159  NC  [R0402]  76.2 63.5 90 bottom
R160  2.2K  [R0402]  75.67 13.84 0 bottom
R161  3.4K  [R0402]  120.9 15.75 270 bottom
R162  2.2K  [R0402]  75.67 14.86 0 bottom
R163  2.2K  [R0402]  93.6 13.08 180 bottom
R164  1K  [R0402]  93.09 54.86 180 top
R165  10K  [R0402]  89.79 54.86 0 top
R166  0R  [R0402]  9.91 11.81 180 top
R167  0R  [R0402]  9.91 31.75 180 top
R168  0R  [R0402]  9.91 23.75 180 bottom
R169  0R  [R0402]  9.91 43.05 180 bottom
R170  0R  [R0402]  9.91 49.91 180 top
R171  15K  [R0402]  129.79 36.7 90 bottom
R172  100K  [R0402]  108.71 27.94 90 bottom
R173  0R  [R0402]  131.95 35.05 0 bottom
R174  0R  [R0402]  129.29 39.62 0 bottom
R175  0R  [R0402]  128.78 36.7 90 bottom
R176  30K  [R0402]  111 27.94 90 bottom
R177  1K  [R0402]  113.16 27.94 270 bottom
R178  10K  [R0402]  112.14 27.94 90 bottom
R179  4.7K  [R0402]  113.16 8.89 90 bottom
R180  22R  [R0402]  114.17 8.89 90 bottom
R181  22R  [R0402]  113.67 10.36 0 bottom
R182  100R  [R0402]  123.06 21.97 90 top
R183  100R  [R0402]  124.08 21.97 90 top
R184  2.2R  [R0402]  129.67 21.97 90 top
R185  2.2R  [R0402]  130.68 21.97 90 top
R186  100R  [R0402]  2.16 79.88 0 top
R187  100R  [R0402]  2.16 66.8 0 top
R188  2.2K  [R0402]  93.6 12.06 180 bottom
R189  2.2K  [R0402]  95.63 18.16 180 bottom
R190  2.2K  [R0402]  95.63 19.18 180 bottom
R191  0R  [R0603]  84.45 9.02 90 bottom
R192  20K  [R0402]  90.04 8.89 90 bottom
R193  1K  [R0402]  95.38 8.89 90 bottom
R194  10K  [R0402]  94.36 8.89 270 bottom
R195  1K  [R0402]  60.83 10.03 0 bottom
R196  3.4K  [R0402]  65.15 10.03 180 bottom
R197  3.4K  [R0402]  76.58 10.03 0 bottom
R198  0R  [R0402]  59.44 40.77 270 bottom
R199  1K  [R0402]  49.15 14.48 270 bottom
R200  1K  [R0402]  76.07 7.24 90 bottom
R201  100R  [R0402]  119.25 8.89 270 bottom
R202  100R  [R0402]  122.05 8.89 270 bottom
R203  100R  [R0402]  127.25 8.89 270 bottom
R204  100R  [R0402]  130.05 8.89 270 bottom
R205  120R  [R0402]  21.84 11.81 180 top
R206  120R  [R0402]  15.24 11.81 180 top
R207  100R  [R0402]  106.43 8.89 270 bottom
R208  100R  [R0402]  103.63 8.89 270 bottom
R209  100R  [R0402]  100.84 8.89 270 bottom
R210  100R  [R0402]  98.04 8.89 270 bottom
R211  120R  [R0402]  36.2 11.81 90 top
R212  10K  [R0402]  37.34 21.97 180 top
R213  4.7K  [R0402]  36.2 14.35 90 bottom
R214  4.7K  [R0402]  36.2 11.81 90 bottom
R215  4.7K  [R0402]  29.72 14.35 90 bottom
R216  120R  [R0402]  29.72 11.81 90 top
R217  10K  [R0402]  30.61 21.97 180 top
R218  4.7K  [R0402]  29.72 11.81 90 bottom
R219  0R  [R0603]  23.24 58.29 90 bottom
R220  NC  [R0603]  26.04 59.05 180 bottom
R221  0R  [R0603]  32.64 58.29 90 bottom
R222  NC  [R0603]  29.84 59.05 0 bottom
R223  20K  [R0402]  32.77 57.78 90 top
R224  20K  [R0402]  31.5 57.78 90 top
R225  1K  [R0402]  28.96 55.37 90 top
R226  10K  [R0402]  28.96 57.78 270 top
R227  499R  [R0402]  100.71 64.52 180 top
R228  499R  [R0402]  102.74 64.52 0 top
R229  499R  [R0402]  92.71 64.52 0 top
R230  499R  [R0402]  90.68 64.52 180 top
R231  499R  [R0402]  104.78 64.52 180 top
R232  499R  [R0402]  106.81 64.52 0 top
R233  499R  [R0402]  96.77 64.52 0 top
R234  499R  [R0402]  94.74 64.52 180 top
R235  2.2K  [R0402]  75.69 15.95 0 bottom
R236  2.2K  [R0402]  75.69 17.07 0 bottom
R237  2.2K  [R0402]  72.14 23.62 0 bottom
R238  2.2K  [R0402]  70.1 23.62 180 bottom
R239  2.2K  [R0402]  53.72 42.16 0 bottom
R240  2.2K  [R0402]  53.72 41.15 0 bottom
R241  10K  [R0402]  21.97 48.39 90 bottom
R242  470R  [R0402]  50.42 74.42 180 bottom
R243  470R  [R0402]  47.24 74.42 180 bottom
SS1  -  [NPTH_M3]  4 86 0 top
SS2  -  [NPTH_M3]  4 4 0 top
SS3  -  [NPTH_M3]  146 4 0 top
SS4  -  [NPTH_M3]  146 86 0 top
SS5  M2.5X1.5mm  [SMTSO-M2R5]  99.92 13.41 0 top
SS6  M2.5X1.5mm  [SMTSO-M2R5]  43.92 13.41 0 top
SS7  M2X4mm  [SMTWE_M2]  136.49 63.06 0 top
SS8  M2X4mm  [SMTWE_M2]  112.29 63.06 0 top
SS9  M2.5X1.5mm  [SMTSO-M2R5]  99.92 47.41 0 top
SS10  M2.5X1.5mm  [SMTSO-M2R5]  43.92 47.41 0 top
SW1  TS-1091B-A7B3-D2  [SW_TH3_4P5X4P5X6P5]  145.42 80.03 90 top
SW2  TS-1091B-A7B3-D2  [SW_TH3_4P5X4P5X6P5]  145.42 74.55 90 top
SW3  TS-1091B-A7B3-D2  [SW_TH3_4P5X4P5X6P5]  145.42 69.06 90 top
U1  ASP9135ZC-R  [SOT23_6]  16.76 64.77 90 top
U2  ASP9135ZC-R  [SOT23_6]  11.18 64.77 90 top
U3  LPW5209AB5F  [SOT23-5]  51.44 13.59 180 bottom
U4  NC  [SMD4-6R80X2R50]  138.84 5.21 180 top
U5  BM8563EMA  [MSOP-8]  29.46 52.32 90 bottom
U6  XC6206P332MR  [SOT-23-3]  35.17 48.39 270 bottom
U7  RTL8211F  [QFP_40P_R]  60.91 62.87 270 top
U8  RTL8211F  [QFP_40P_R]  79.32 62.87 270 top
U9  ES8388  [QFN28_0R45-4X4EP2R6X2R6]  48.13 62.87 0 top
U10  NS4110B  [SOP-8-EP-2R5X3R4]  30.86 62.87 0 top
U11  FUSB302BMPX  [WQFN14-0R50-2R5X2R5EP1R45X1R45]  38.94 66.34 180 bottom
U12  LPW5209AB5F  [SOT23-5]  29.46 77.85 90 bottom
U13  LPW5209AB5F  [SOT23-5]  116.08 87 180 bottom
U14  RCLAMP0524P  [USON_10]  24.51 80.01 0 top
U15  RCLAMP0524P  [USON_10]  118.36 71.75 0 top
U16  RCLAMP0524P  [USON_10]  31.37 80.01 0 top
U17  RCLAMP0524P  [USON_10]  113.54 71.75 0 top
U18  RCLAMP0524P  [USON_10]  134.37 71.75 0 top
U19  FE2.1-CQFP48A  [LQFP48_0P5_7X7]  125.22 62.87 270 top
U20  LPW5209AB5F  [SOT23-5]  132.46 87 180 bottom
U22  TL8821CUB  [RL-UM02WBS-8723BU]  130.56 37.82 180 top
U24  LPW5209AB5F  [SOT23-5]  116.59 16.76 180 bottom
U25  LPW5209AB5F  [SOT23-5]  123.19 16.76 180 bottom
U26  ASP9135ZC-R  [SOT23_6]  110.95 24.28 180 bottom
U27  NUP5120X6T1G  [SOT563]  131.95 37.85 90 bottom
U28  74LVC1G125GW  [SOT-353]  5.33 79.13 90 top
U29  74LVC1G125GW  [SOT-353]  5.33 67.44 270 top
U31  LPW5209AB5F  [SOT23-5]  68.33 8.89 90 bottom
U32  LPW5209AB5F  [SOT23-5]  73.03 8.89 90 bottom
U33  SIT3232EESE  [SOIC16]  18.92 28.83 90 top
U34  SIT1042AQT/3  [SOP8]  23.62 17.53 180 top
U35  SIT1042AQT/3  [SOP8]  16.26 17.53 180 top
U36  SIT3088EESA  [SOP8]  37.34 17.53 180 top
U37  SIT3088EESA  [SOP8]  30.61 17.53 180 top
U38  NS4110B  [SOP-8-EP-2R5X3R4]  25.02 62.87 0 top
Y1  32.768KHz  [3215]  23.5 52.32 90 bottom
Y2  25MHz  [3225]  69.04 63.88 270 top
Y3  25MHz  [3225]  87.45 63.88 270 top
Y4  12MHz  [3225]  118.36 55.63 180 top

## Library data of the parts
C1-C3 C5-C96 C103 C104 C107-C134 C136-C169 C172-C177 C180-C215 C226 = CAP_NP
C4 C135 = CAP
C97-C102 C105 C106 C170 C171 = CAP_NP: signal model: CAP_NP_C0402_DISCRETE_0.1UF_0.1uF
C216-C223 = CAP_NP: signal model: CAP_NP_C0402_DISCRETE_0.22UF_0.22uF
C224 C225 = CAP_NP: signal model: CAP_NP_C0402_DISCRETE_1UF_1uF
CN1 = WIFI_ANT
CN2 CN3 = B2B_2X40
CN4 CN5 = DF40C-80DP-0.4V
D1 = DIODE
D2-D8 D10-D17 D19-D30 D32-D35 D37-D40 D43 D45-D48 D57 D58 = DIODE BI-DIR TRIG
D9 = BAT54C
D18 D36 D41 D42 D59 D60 = DIODE_SCHTKY
D31 D44 D55 D56 = DIODE BI-DIR TRIG: signal model: DIODE_BI-DIR_TRIG_R0201_D1250-5R5C_D1250-5R5C
D49-D54 = DIODE BI-DIR TRIG: signal model: DIODE_BI-DIR_TRIG_R0201_TPESD0201G05V_TPESD0201G05V
DN1 DN2 = TVS Arr ComA
F1 = FUSE
J1 = DC-044A-20A
J2 J5 J9 J22 = 1X2PIN
J4 = TF_Card
J6 J7 = HY911130A
J8 = PJ-393
J10 = TYPE-C-24P
J11 = USB3D0_USB2D0-A-D
J12 = USB-A-D
J13 = FPC-30P
J14-J18 = FPC-24P
J19 = SIM-7-1
J20 = MINI-PCIE
J21 = 1X3PIN
J23 J30 = 1X6PIN
J24 = CON6
J25 J26 = 1X4PIN
J27 J28 = 2X3PIN
J29 J31 = CON4
J32 = 2X9PIN
J33 = HDMI-001C
L1 L3 L4 L6 L14 = IND
L2 L5 L7-L12 L15-L21 L27 = BEAD
LED1 LED2 = LED
P1 = MIC_POM
Q1 Q11 Q15 Q16 = MOSFET_P
Q2 Q17 = NPN
Q3 Q6-Q10 Q12 Q18-Q21 = 2SK3018
Q4 Q5 = MOSFET N
R1-R16 R21 R27 R30-R35 R38 R43-R48 R50-R59 R62 R65 R66 R69-R72 R74-R104 R109 R118-R130 R133-R137 R139-R142 R144-R173 R175-R179 R182 R183 R186-R243 = RES
R17-R20 R22-R26 R36 R37 R39-R42 R49 R60 R61 R63 R64 R67 R68 R73 R180 R181 = RES: signal model: RES_R0402_DISCRETE_22R_22R
R105-R108 R110-R117 R131 R132 R138 R143 R174 = RES: signal model: RES_R0402_DISCRETE_0R_0R
R184 R185 = RES: signal model: RES_R0402_DISCRETE_2.2R_2.2R
SS1-SS10 = SPACER
SW1-SW3 = SW_TH3P
U1 U2 U26 = TP6327GS6
U3 U12 U13 U20 U24 U25 U31 U32 = LPW5209AB5F
U4 = IRM-V838M3-C/TR1
U5 = HYM8563S
U6 = LDO-3P
U7 U8 = RTL8211F
U9 = ES8388
U10 U38 = NS4110B
U11 = FUSB302BMPX
U14-U18 = RCLAMP0524P
U19 = FE2.1-CQFP48A
U22 = RTL8723
U27 = NUP5120-D
U28 U29 = 74LVC1G125
U33 = MAX3232CSE
U34 U35 = TJA1057GT3_8P
U36 U37 = SIT3088E-8P
Y1 = CRYSTAL_2P
Y2-Y4 = CRYSTAL_4P

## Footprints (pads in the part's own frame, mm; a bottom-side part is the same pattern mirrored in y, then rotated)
3215
  rect 1.4x1.2 smd: 1(-1.001,0) 2(1.001,0)
3225
  rect 1.3x1 smd: 1(-1.15,-0.75) 2(1.15,-0.75) 3(1.15,0.75) 4(-1.15,0.75)
AV7_6X14R50_TM
  round 1.2 hole 1.2 unplated: (0,3.5) (0,-3.5)
  oval 1.2x2 hole 0.75x1.5: 1(-2.3,3.2) 2(-2.3,0.1) 3(-2.3,-2.7) 4(2.3,-3.1) 6(2.3,2) 7(2.3,-0.8) 8(-2.3,-5)
C0402
  rect 0.599x0.599 smd: 1(-0.5,0) 2(0.5,0)
C0805
  rect 1.16x1.47 smd: 1(-0.89,0) 2(0.89,0)
C1206
  rect 1.2x1.9 smd: 1(-1.6,0) 2(1.6,0)
CASE-B_3528
  rect 1.2x2.4 smd: 1(-1.45,0) 2(1.45,0)
DB2ERC-3P81-4P
  rect 1.8x1.8 hole 1.2: 1(-5.715,0)
  round 1.8 hole 1.2: 2(-1.905,0) 3(1.905,0) 4(5.715,0)
DB2ERC-3P81-6P
  rect 1.8x1.8 hole 1.2: 1(-9.525,0)
  round 1.8 hole 1.2: 2(-5.715,0) 3(-1.905,0) 4(1.905,0) 5(5.715,0) 6(9.525,0)
DC_IN_TH_3P_10R1X11R6
  round 1.999 hole 1.999 unplated: (-1.699,-1.25)
  oval 2.4x1.001 hole 1.801x0.399: 1(-2.751,-4.9) 5(-2.751,4.9)
  oval 2.7x1.5 hole 1.7x0.5: 2(4.501,-1.25) 3(4.501,4.049) 4(4.501,-4.45)
DF40C-80DP-0P4V
  rect 0.23x0.66 smd: 1(-7.8,1.355) 2(-7.8,-1.355) 3(-7.4,1.355) 4(-7.4,-1.355) 5(-7,1.355) 6(-7,-1.355) 7(-6.6,1.355) 8(-6.6,-1.355) 9(-6.2,1.355) 10(-6.2,-1.355) 11(-5.8,1.355) 12(-5.8,-1.355) 13(-5.4,1.355) 14(-5.4,-1.355) 15(-5,1.355) 16(-5,-1.355) 17(-4.6,1.355) 18(-4.6,-1.355) 19(-4.2,1.355) 20(-4.2,-1.355) 21(-3.8,1.355) 22(-3.8,-1.355) 23(-3.4,1.355) 24(-3.4,-1.355) 25(-3,1.355) 26(-3,-1.355) 27(-2.6,1.355) 28(-2.6,-1.355) 29(-2.2,1.355) 30(-2.2,-1.355) 31(-1.8,1.355) 32(-1.8,-1.355) 33(-1.4,1.355) 34(-1.4,-1.355) 35(-1,1.355) 36(-1,-1.355) 37(-0.6,1.355) 38(-0.6,-1.355) 39(-0.2,1.355) 40(-0.2,-1.355) 41(0.2,1.355) 42(0.2,-1.355) 43(0.6,1.355) 44(0.6,-1.355) 45(1,1.355) 46(1,-1.355) 47(1.4,1.355) 48(1.4,-1.355) 49(1.8,1.355) 50(1.8,-1.355) 51(2.2,1.355) 52(2.2,-1.355) 53(2.6,1.355) 54(2.6,-1.355) 55(3,1.355) 56(3,-1.355) 57(3.4,1.355) 58(3.4,-1.355) 59(3.8,1.355) 60(3.8,-1.355) 61(4.2,1.355) 62(4.2,-1.355) 63(4.6,1.355) 64(4.6,-1.355) 65(5,1.355) 66(5,-1.355) 67(5.4,1.355) 68(5.4,-1.355) 69(5.8,1.355) 70(5.8,-1.355) 71(6.2,1.355) 72(6.2,-1.355) 73(6.6,1.355) 74(6.6,-1.355) 75(7,1.355) 76(7,-1.355) 77(7.4,1.355) 78(7.4,-1.355) 79(7.8,1.355) 80(7.8,-1.355)
  rect 0.35x0.66 smd: 81(-8.275,1.355) 82(-8.275,-1.355) 83(8.275,-1.355) 84(8.275,1.355)
DF40C-80DS-0P4V
  rect 0.2x1 smd: 1(-7.8,-1.27) 2(-7.8,1.24) 3(-7.4,-1.27) 4(-7.4,1.24) 5(-7,-1.27) 6(-7,1.24) 7(-6.6,-1.27) 8(-6.6,1.24) 9(-6.2,-1.27) 10(-6.2,1.24) 11(-5.8,-1.27) 12(-5.8,1.24) 13(-5.4,-1.27) 14(-5.4,1.24) 15(-5,-1.27) 16(-5,1.24) 17(-4.6,-1.27) 18(-4.6,1.24) 19(-4.2,-1.27) 20(-4.2,1.24) 21(-3.8,-1.27) 22(-3.8,1.24) 23(-3.4,-1.27) 24(-3.4,1.24) 25(-3,-1.27) 26(-3,1.24) 27(-2.6,-1.27) 28(-2.6,1.24) 29(-2.2,-1.27) 30(-2.2,1.24) 31(-1.8,-1.27) 32(-1.8,1.24) 33(-1.4,-1.27) 34(-1.4,1.24) 35(-1,-1.27) 36(-1,1.24) 37(-0.6,-1.27) 38(-0.6,1.24) 39(-0.2,-1.27) 40(-0.2,1.24) 41(0.2,-1.27) 42(0.2,1.24) 43(0.6,-1.27) 44(0.6,1.24) 45(1,-1.27) 46(1,1.24) 47(1.4,-1.27) 48(1.4,1.24) 49(1.8,-1.27) 50(1.8,1.24) 51(2.2,-1.27) 52(2.2,1.24) 53(2.6,-1.27) 54(2.6,1.24) 55(3,-1.27) 56(3,1.24) 57(3.4,-1.27) 58(3.4,1.24) 59(3.8,-1.27) 60(3.8,1.24) 61(4.2,-1.27) 62(4.2,1.24) 63(4.6,-1.27) 64(4.6,1.24) 65(5,-1.27) 66(5,1.24) 67(5.4,-1.27) 68(5.4,1.24) 69(5.8,-1.27) 70(5.8,1.24) 71(6.2,-1.27) 72(6.2,1.24) 73(6.6,-1.27) 74(6.6,1.24) 75(7,-1.27) 76(7,1.24) 77(7.4,-1.27) 78(7.4,1.24) 79(7.8,-1.27) 80(7.8,1.24)
EC6P3
  rect 1.001x1.999 smd: 1(0,2.8) 2(0,-2.8)
ES0402
  rect 0.5x0.5 smd: 1(-0.45,0) 2(0.45,0)
ESD0402
  rect 0.599x0.599 smd: 1(-0.5,0) 2(0.5,0)
F1812
  rect 1.78x3.3 smd: 1(-2.305,0) 2(2.305,0)
FPC-30P-0P5
  rect 0.3x1.3 smd: 1(-7.25,1.35) 2(-6.75,1.35) 3(-6.25,1.35) 4(-5.75,1.35) 5(-5.25,1.35) 6(-4.75,1.35) 7(-4.25,1.35) 8(-3.75,1.35) 9(-3.25,1.35) 10(-2.75,1.35) 11(-2.25,1.35) 12(-1.75,1.35) 13(-1.25,1.35) 14(-0.75,1.35) 15(-0.25,1.35) 16(0.25,1.35) 17(0.75,1.35) 18(1.25,1.35) 19(1.75,1.35) 20(2.25,1.35) 21(2.75,1.35) 22(3.25,1.35) 23(3.75,1.35) 24(4.25,1.35) 25(4.75,1.35) 26(5.25,1.35) 27(5.75,1.35) 28(6.25,1.35) 29(6.75,1.35) 30(7.25,1.35)
  rect 1.6x2 smd: 31(9.4,-1.35) 32(-9.4,-1.35)
FPC_24P_0P5
  rect 0.3x1.3 smd: 1(-5.75,-1.351) 2(-5.25,-1.351) 3(-4.75,-1.351) 4(-4.25,-1.351) 5(-3.75,-1.351) 6(-3.25,-1.351) 7(-2.75,-1.351) 8(-2.25,-1.351) 9(-1.75,-1.351) 10(-1.25,-1.351) 11(-0.75,-1.351) 12(-0.25,-1.351) 13(0.25,-1.351) 14(0.75,-1.351) 15(1.25,-1.351) 16(1.75,-1.351) 17(2.25,-1.351) 18(2.75,-1.351) 19(3.25,-1.351) 20(3.75,-1.351) 21(4.25,-1.351) 22(4.75,-1.351) 23(5.25,-1.351) 24(5.75,-1.351)
  rect 1.6x2 smd: 25(7.45,1.351) 26(-7.45,1.351)
GH1P25_TH_2P
  rect 0.9x0.9 hole 0.5: 1(-0.625,0)
  round 0.9 hole 0.5: 2(0.625,0)
HDMI-SMD
  round 1.999 hole 1.999 unplated: (-6.05,-2) (7.2,1.5)
  round 0.8 hole 0.55: 1(5.3,0.5) 2(4.731,-0.5) 3(4.145,0.5) 4(3.575,-0.5) 5(2.99,0.5) 6(2.419,-0.5) 7(1.835,0.5) 8(1.263,-0.5) 9(0.68,0.5) 10(0.107,-0.5) 11(-0.475,0.5) 12(-1.049,-0.5) 13(-1.63,0.5) 14(-2.205,-0.5) 15(-2.785,0.5) 16(-3.361,-0.5) 17(-3.94,0.5) 18(-4.517,-0.5) 19(-5.095,0.5)
  oval 3.2x1.4 hole 2.7x0.9: G1(-6.05,3.25) G2(3.45,3.25) G3(-2.95,-3.25) G4(6.05,-3.25)
HDR1X3-2R54-TM-VM
  rect 1.6x1.6 hole 1: 1(-2.54,0)
  round 1.6 hole 1: 2(0,0) 3(2.54,0)
HDR2X3-2R54-TM-VM
  rect 1.6x1.6 hole 1: 1(-2.54,-1.27)
  round 1.6 hole 1: 2(-2.54,1.27) 3(0,-1.27) 4(0,1.27) 5(2.54,-1.27) 6(2.54,1.27)
HDR2X9-2R54-TM-VM
  rect 1.6x1.6 hole 1: 1(-10.16,-1.27)
  round 1.6 hole 1: 2(-10.16,1.27) 3(-7.62,-1.27) 4(-7.62,1.27) 5(-5.08,-1.27) 6(-5.08,1.27) 7(-2.54,-1.27) 8(-2.54,1.27) 9(0,-1.27) 10(0,1.27) 11(2.54,-1.27) 12(2.54,1.27) 13(5.08,-1.27) 14(5.08,1.27) 15(7.62,-1.27) 16(7.62,1.27) 17(10.16,-1.27) 18(10.16,1.27)
HY911130A
  round 3.25 hole 3.25 unplated: (-5.715,0) (5.715,0)
  round 1.6 hole 1: 1(5.72,-8.89) 2(4.45,-6.35) 3(3.18,-8.89) 4(1.91,-6.35) 5(0.64,-8.89) 6(-0.63,-6.35) 7(-1.9,-8.89) 8(-3.17,-6.35) 9(-4.44,-8.89) 10(-5.71,-6.35)
  round 1.8 hole 1.2: 11(6.625,4.9) 12(4.085,4.9) 13(-4.085,4.9) 14(-6.625,4.9)
  round 2.43 hole 1.83: 15(7.745,-3.05) 16(-7.745,-3.05)
L0402
  rect 0.599x0.599 smd: 1(-0.5,0) 2(0.5,0)
L0603
  rect 0.8x0.8 smd: 1(-0.8,0) 2(0.8,0)
L2520
  rect 1.118x2.032 smd: 1(-0.959,0) 2(0.959,0)
L4520
  rect 1.4x2.3 smd: 1(-1.8,0) 2(1.8,0)
LED_HS_0602_UR
  rect 0.77x0.599 smd: 1(-0.815,0) 2(0.815,0)
LQFP48_0P5_7X7
  rect 1.2x0.25 smd: 1(-4.25,2.75) 2(-4.25,2.25) 3(-4.25,1.75) 4(-4.25,1.25) 5(-4.25,0.75) 6(-4.25,0.25) 7(-4.25,-0.25) 8(-4.25,-0.75) 9(-4.25,-1.25) 10(-4.25,-1.75) 11(-4.25,-2.25) 12(-4.25,-2.75) 25(4.25,-2.751) 26(4.25,-2.251) 27(4.25,-1.751) 28(4.25,-1.251) 29(4.25,-0.751) 30(4.25,-0.251) 31(4.25,0.249) 32(4.25,0.749) 33(4.25,1.249) 34(4.25,1.749) 35(4.25,2.249) 36(4.25,2.749)
  rect 0.25x1.2 smd: 13(-2.75,-4.25) 14(-2.25,-4.25) 15(-1.75,-4.25) 16(-1.25,-4.25) 17(-0.75,-4.25) 18(-0.25,-4.25) 19(0.25,-4.25) 20(0.75,-4.25) 21(1.25,-4.25) 22(1.75,-4.25) 23(2.25,-4.25) 24(2.75,-4.25) 37(2.75,4.25) 38(2.25,4.25) 39(1.75,4.25) 40(1.25,4.25) 41(0.75,4.25) 42(0.25,4.25) 43(-0.25,4.25) 44(-0.75,4.25) 45(-1.25,4.25) 46(-1.75,4.25) 47(-2.25,4.25) 48(-2.75,4.25)
MIC2-4R00-TM
  round 1.1 hole 0.7: 1(-0.7,0) 2(0.7,0)
MSOP-8
  rect 0.3x1 smd: 1(-0.975,-2.2) 2(-0.325,-2.2) 3(0.325,-2.2) 4(0.975,-2.2) 5(0.975,2.2) 6(0.325,2.2) 7(-0.325,2.2) 8(-0.975,2.2)
NANO_SIM
  round 0.9 hole 0.9 unplated: (-5,-5.49) (3.5,-5.49)
  rect 0.5x1.3 smd: 1(0.25,6.74) 2(-2.29,6.74) 3(-4.83,6.74) 4(2.47,6.74) 5(1.52,6.74) 6(-1.02,6.74) 7(-3.56,6.74)
  rect 1x2.1 smd: 8(-6.5,5.26) 9(6.5,5.26) 10(-6.5,-6.74) 11(6.5,-6.74)
NPTH_M3
  round 3.2 hole 3.2 unplated: (0,0)
PCIE_52P
  round 1.6 hole 1.6 unplated: (-12.5,0)
  round 1.1 hole 1.1 unplated: (12.5,0)
  rect 0.6x2 smd: 1(-11.8,-4.1) 2(-11.4,4.1) 3(-11,-4.1) 4(-10.6,4.1) 5(-10.2,-4.1) 6(-9.8,4.1) 7(-9.4,-4.1) 8(-9,4.1) 9(-8.6,-4.1) 10(-8.2,4.1) 11(-7.8,-4.1) 12(-7.4,4.1) 13(-7,-4.1) 14(-6.6,4.1) 15(-6.2,-4.1) 16(-5.8,4.1) 17(-2.2,-4.1) 18(-1.8,4.1) 19(-1.4,-4.1) 20(-1,4.1) 21(-0.6,-4.1) 22(-0.2,4.1) 23(0.2,-4.1) 24(0.6,4.1) 25(1,-4.1) 26(1.4,4.1) 27(1.8,-4.1) 28(2.2,4.1) 29(2.6,-4.1) 30(3,4.1) 31(3.4,-4.1) 32(3.8,4.1) 33(4.2,-4.1) 34(4.6,4.1) 35(5,-4.1) 36(5.4,4.1) 37(5.8,-4.1) 38(6.2,4.1) 39(6.6,-4.1) 40(7,4.1) 41(7.4,-4.1) 42(7.8,4.1) 43(8.2,-4.1) 44(8.6,4.1) 45(9,-4.1) 46(9.4,4.1) 47(9.8,-4.1) 48(10.2,4.1) 49(10.6,-4.1) 50(11,4.1) 51(11.4,-4.1) 52(11.8,4.1)
  rect 2.15x2.6 smd: 53(14.65,-3.5) 54(-14.65,-3.5)
PH-1X2-2P0_L
  rect 1.1x1.1 hole 0.7: 1(-1,0)
  round 1.1 hole 0.7: 2(1,0)
PH-1X4-2P0
  rect 1.1x1.1 hole 0.7: 1(-3,0)
  round 1.1 hole 0.7: 2(-1,0) 3(1,0) 4(3,0)
PH-1X6-2P0
  rect 1.1x1.1 hole 0.7: 1(-5,0)
  round 1.1 hole 0.7: 2(-3,0) 3(-1,0) 4(1,0) 5(3,0) 6(5,0)
QFN28_0R45-4X4EP2R6X2R6
  oval 0.8x0.2 smd: 1(-2,1.35)
  rect 0.8x0.2 smd: 2(-2,0.9) 3(-2,0.45) 4(-2,0) 5(-2,-0.45) 6(-2,-0.9) 7(-2,-1.35) 15(2,-1.35) 16(2,-0.9) 17(2,-0.45) 18(2,0) 19(2,0.45) 20(2,0.9) 21(2,1.35)
  rect 0.2x0.8 smd: 8(-1.35,-2) 9(-0.9,-2) 10(-0.45,-2) 11(0,-2) 12(0.45,-2) 13(0.9,-2) 14(1.35,-2) 22(1.35,2) 23(0.9,2) 24(0.45,2) 25(0,2) 26(-0.45,2) 27(-0.9,2) 28(-1.35,2)
  rect 2x2 smd: 29(0,0)
QFP_40P_R
  oval 0.8x0.2 smd: 1(-2.5,1.8) 2(-2.5,1.4) 3(-2.5,1) 4(-2.5,0.6) 5(-2.5,0.2) 6(-2.5,-0.2) 7(-2.5,-0.6) 8(-2.5,-1) 9(-2.5,-1.4) 10(-2.5,-1.8) 21(2.5,-1.8) 22(2.5,-1.4) 23(2.5,-1) 24(2.5,-0.6) 25(2.5,-0.2) 26(2.5,0.2) 27(2.5,0.6) 28(2.5,1) 29(2.5,1.4) 30(2.5,1.8)
  oval 0.2x0.8 smd: 11(-1.8,-2.5) 12(-1.4,-2.5) 13(-1,-2.5) 14(-0.6,-2.5) 15(-0.2,-2.5) 16(0.2,-2.5) 17(0.6,-2.5) 18(1,-2.5) 19(1.4,-2.5) 20(1.8,-2.5) 31(1.8,2.5) 32(1.4,2.5) 33(1,2.5) 34(0.6,2.5) 35(0.2,2.5) 36(-0.2,2.5) 37(-0.6,2.5) 38(-1,2.5) 39(-1.4,2.5) 40(-1.8,2.5)
  rect 3x3 smd: 41(0,0)
R0201
  rect 0.35x0.35 smd: 1(-0.275,0) 2(0.275,0)
R0402
  rect 0.599x0.599 smd: 1(-0.5,0) 2(0.5,0)
R0603
  rect 0.8x0.8 smd: 1(-0.8,0) 2(0.8,0)
R0805
  rect 1.016x1.143 smd: 1(-1.016,0) 2(1.016,0)
RL-UM02WBS-8723BU
  oval 2x1 smd: 1(-6.3,3.97) 2(-6.3,1.97) 3(-6.3,-1.01) 4(-6.3,-3.17) 5(6.3,3.5) 6(6.3,0.97) 7(6.3,-2.53) 8(6.3,-5.33)
  oval 1x2 smd: 9(3.65,-6.9) 10(2.38,-6.9) 11(1.11,-6.9) 12(-0.16,-6.9) 13(-1.43,-6.9) 14(-2.7,-6.9)
SMD4-6R80X2R50
  rect 0.8x1.2 smd: 1(1.905,0) 2(0.635,0) 3(-0.635,0) 4(-1.905,0)
SMTSO-M2R5
  round 6.2 hole 4.22: 1(0,0)
SMTWE_M2
  round 5.3 hole 3: 1(0,0)
SOD323_T
  rect 0.8x0.8 smd: 1(-1.175,0) 2(1.175,0)
SOD523
  rect 0.6x0.7 smd: 1(-0.71,0) 2(0.71,0)
SOD-123
  rect 1.2x1.4 smd: 1(1.7,0) 2(-1.7,0)
SOIC16
  oval 2.032x0.61 smd: 1(-2.789,4.44) 2(-2.789,3.18) 3(-2.789,1.9) 4(-2.789,0.64) 5(-2.789,-0.64) 6(-2.789,-1.9) 7(-2.789,-3.18) 8(-2.789,-4.44) 9(2.789,-4.44) 10(2.789,-3.18) 11(2.789,-1.9) 12(2.789,-0.64) 13(2.789,0.64) 14(2.789,1.9) 15(2.789,3.18) 16(2.789,4.44)
SOP8
  oval 0.6x1.8 smd: 1(-1.905,-2.5) 2(-0.635,-2.5) 3(0.635,-2.5) 4(1.905,-2.5) 5(1.905,2.5) 6(0.635,2.5) 7(-0.635,2.5) 8(-1.905,2.5)
SOP-8-EP-2R5X3R4
  oval 0.4x1.4 smd: 1(-1.905,-2.6) 2(-0.635,-2.6) 3(0.635,-2.6) 4(1.905,-2.6) 5(1.905,2.6) 6(0.635,2.6) 7(-0.635,2.6) 8(-1.905,2.6)
  rect 3.3x2.4 smd: 9(0,0)
SOT23
  rect 0.914x0.914 smd: 1(-0.953,-0.991) 2(0.953,-0.991)
  rect 0.914x1.27 smd: 3(0,1.041)
SOT23-5
  rect 0.599x1.199 smd: 1(-0.95,-1.25) 2(0,-1.25) 3(0.95,-1.25) 4(0.95,1.25) 5(-0.95,1.25)
SOT23_6
  rect 0.7x0.9 smd: 1(-0.95,-1.2) 2(0,-1.2) 3(0.95,-1.2) 4(0.95,1.2) 5(0,1.2) 6(-0.95,1.2)
SOT563
  rect 0.3x0.45 smd: 1(-0.5,-0.675) 2(0,-0.675) 3(0.5,-0.675) 4(0.5,0.675) 5(0,0.675) 6(-0.5,0.675)
SOT-23-3
  rect 0.914x0.914 smd: 1(-0.953,-0.991) 2(0.953,-0.991)
  rect 0.914x1.27 smd: 3(0,1.041)
SOT-353
  rect 0.406x1.194 smd: 1(-0.65,-0.9) 2(0,-0.9) 3(0.65,-0.9) 4(0.65,0.9) 5(-0.65,0.9)
SW_TH3_4P5X4P5X6P5
  round 1.4 hole 0.8: 1(-1.55,0.975) 2(1.55,0.975) 3(0,-0.975)
TFCARD
  round 1 hole 1 unplated: (-4,0) (4,0)
  rect 0.7x1.6 smd: 1(3.2,10.5) 2(2.1,10.5) 3(1,10.5) 4(-0.1,10.5) 5(-1.2,10.5) 6(-2.3,10.5) 7(-3.4,10.5) 8(-4.5,10.5) 9(-5.6,10.5)
  rect 1.2x1.778 smd: 10(-6.8,10)
  rect 1.524x2.413 smd: 11(-6.8,0.4) 12(8.7,0.4)
  rect 1.778x1.778 smd: 13(7.8,10)
UFL-3
  rect 1.05x1.05 smd: 1(0,-1.5)
  rect 1.05x2.2 smd: 2(-1.5,0) 3(1.5,0)
unnamed#2
  round 1.016 smd: (0,0)
USB3D0-AF-18P
  round 1.1 hole 0.7: 1(-3.5,-1.501) 2(-1.001,-1.501) 3(1.001,-1.501) 4(3.5,-1.501) 5(4,0) 6(1.999,0) 7(0,0) 8(-1.999,0) 9(-4,0) 10(-3.5,1.699) 11(-1.001,1.699) 12(1.001,1.699) 13(3.5,1.699) 14(4,3.2) 15(1.999,3.2) 16(0,3.2) 17(-1.999,3.2) 18(-4,3.2)
  round 3.2 hole 2.4: 19(6.571,-3.5) 20(6.571,2.179) 21(-6.571,2.179) 22(-6.571,-3.5)
USB-A-D
  round 1.6 hole 1: 1(3.5,-6.5) 2(1,-6.5) 3(-1,-6.5) 4(-3.5,-6.5) 7(3.5,-3.5) 8(1,-3.5) 9(-1,-3.5) 10(-3.5,-3.5)
  round 2.6 hole 2: 5(-6.55,-6.5) 6(6.55,-6.5) 11(-6.55,-0.7) 12(6.55,-0.7)
USB-C-SMD_TYC-324G
  oval 1.5x1 hole 1.2x0.5: (-4.06,1.45) (4.06,1.45)
  round 0.5 hole 0.5 unplated: (-3.4,0.57) (3.4,0.57)
  oval 1x2.2 hole 0.6x1.6: 1(-4.32,1.93) 4(4.32,1.93)
  oval 1.2x2.4 hole 0.6x1.9: 2(-4.32,-2.62) 3(4.32,-2.62)
  rect 0.3x1 smd: A1(-2.62,2.62) A2(-2.13,2.62) A3(-1.63,2.62) A4(-1.13,2.62) A5(-0.62,2.62) A6(-0.12,2.62) A7(0.38,2.62) A8(0.88,2.62) A9(1.37,2.62) A10(1.87,2.62) A11(2.37,2.62) A12(2.88,2.62) B1(2.63,1.28) B2(2.13,1.28) B3(1.63,1.28) B4(1.13,1.28) B5(0.62,1.28) B6(0.12,1.28) B7(-0.38,1.28) B8(-0.87,1.28) B9(-1.37,1.28) B10(-1.87,1.28) B11(-2.37,1.28) B12(-2.88,1.28)
USON_10
  rect 0.2x0.7 smd: 1(-1,-0.45) 2(-0.5,-0.45) 4(0.5,-0.45) 5(1,-0.45) 6(1,0.45) 7(0.5,0.45) 9(-0.5,0.45) 10(-1,0.45)
  rect 0.4x0.7 smd: 3(0,-0.45) 8(0,0.45)
WQFN14-0R50-2R5X2R5EP1R45X1R45
  rect 0.6x0.3 smd: 1(-1.21,0.5) 2(-1.21,0) 3(-1.21,-0.5) 8(1.21,-0.5) 9(1.21,0) 10(1.21,0.5)
  rect 0.3x0.6 smd: 4(-0.75,-1.21) 5(-0.25,-1.21) 6(0.25,-1.21) 7(0.75,-1.21) 11(0.75,1.21) 12(0.25,1.21) 13(-0.25,1.21) 14(-0.75,1.21)
  rect 1.2x1.2 smd: 15(0,0)
ZH1P5MM_TH_2P
  round 1.05 hole 0.65: 1(-0.75,0) 2(0.75,0)

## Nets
